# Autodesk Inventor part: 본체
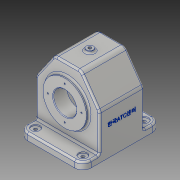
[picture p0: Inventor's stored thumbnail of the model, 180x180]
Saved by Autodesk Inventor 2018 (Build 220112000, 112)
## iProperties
Created: 2022-12
Part Number: 본체
Material: 알루미늄 6061
Document SubType Name: Modeling
Designer: 강의실04
Density: 2.7 g/cm^3
Appearance: 알루미늄 - 평지
Mass: 937.278 g
Surface Area: 1065.24 cm^2
Volume: 347.14 cm^3
Author: 강의실04
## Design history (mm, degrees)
sketch "스케치1"
  geometry: L1 (-55, 12)-(55, 12); L2 (55, 12)-(55, -65); L3 (55, -65)-(-55, -65); L4 (-55, -65)-(-55, 12); L5 (-55, 12)-(-23.491, 57); L6 (-23.491, 57)-(23.491, 57); L7 (23.491, 57)-(55, 12); 3 further points
  constraints: 14 end point, 2 horizontal, 2 midpoint, 2 parallel, 2 vertical alignment, 1 perpendicular
  dimensions: "d1" = 65 distance from line of L3 point (0, 0); "d2" = 77 distance of L3.end L1.start; "d3" = 110 distance of L2.end L3.end; "d4" = 35 deg angle of L5 L4; "d5" = 122 distance between parallel lines of L3 L6
extrude "돌출1" new body sketch "스케치1" stored distance "d6" = 77; taper "d7" = 0 deg
feature "쉘1" dims "d8" = 5
sketch "스케치2"
  geometry: L1 (5, -5)-(5, -72) reference; L2 (5, -72)-(105, -72) reference; L3 (105, -72)-(105, -5) reference; L4 (105, -5)-(5, -5) reference; L5 (0, -77)-(0, 0) reference; L6 (0, 0)-(110, 0) reference; L7 (110, 0)-(110, -77) reference; L8 (110, -77)-(0, -77) reference; L9 (0, -105.5)-(110, -105.5); L10 (110, -105.5)-(110, 28.5); L11 (110, 28.5)-(0, 28.5); L12 (0, 28.5)-(0, -105.5); L13 (0, -105.5)-(110, 28.5); L14 (110, -105.5)-(0, 28.5); 1 further point
  constraints: 12 end point, 2 midpoint, 2 parallel, 1 horizontal, 1 perpendicular, 1 point on line
  dimensions: "d9" = 134 distance of L9.end L10.end
extrude "돌출2" join sketch "스케치2" distance "d10" = 12; taper "d11" = 0 deg
node "작업 평면1"
sketch "스케치3"
  geometry: C1 r 6 at (0, 0); 1 further point
  constraints: 1 centre point, 1 coincident
  dimensions: "d13" = 12 diameter of C1
extrude "돌출3" join sketch "스케치3" stored distance "d14" = 12; taper "d15" = 0 deg
sketch "스케치4"
  geometry: 1 further point
hole "구멍1" sketch "스케치4" at (0, 0) diameter "d16" = 5.188; stored, may be unused: countersink angle "d20" = 90 deg, drill point angle "d22" = 118 deg; dims "d17" = 12, "d18" = 4, "d19" = 2, "d21" = 16
sketch "스케치5"
  geometry: C1 r 37.5 at (0, 0); 1 further point
  constraints: 1 centre point, 1 coincident
  dimensions: "d23" = 75 diameter of C1
extrude "돌출4" join sketch "스케치5" distance "d24" = 5; taper "d25" = 0 deg
sketch "스케치6"
  geometry: C1 r 31 at (0, 0); 1 further point
  constraints: 1 centre point, 1 coincident
  dimensions: "d26" = 62 diameter of C1
extrude "돌출5" join sketch "스케치6" distance "d27" = 10; taper "d28" = 0 deg
sketch "스케치7"
  geometry: L1 (10.424, 33.5)-(-65, 33.5) reference; L2 (0, 33.5)-(0, 0); L3 (52, 33.5)-(10.424, 33.5) reference; L4 (41, 33.5)-(27, 19.5); L5 (27, 19.5)-(0, 19.5); L6 (37.5, 43.5)-(-37.5, 43.5) reference; L7 (41, 33.5)-(0, 33.5)
  constraints: 8 end point, 3 point on line, 2 perpendicular, 1 vertical
  dimensions: "d29" = 54 diameter of L4.end L2; "d30" = 135 deg angle of L3 L4; "d31" = 24 distance between parallel lines of L5 L6
revolve "회전1" sketch "스케치7" stored, may be unused: angle "d32" = 90 deg
sketch "스케치8"
  geometry: C1 r 20 at (0, 0); 1 further point
  constraints: 1 centre point, 1 coincident
  dimensions: "d33" = 40 diameter of C1
extrude "돌출6" cut sketch "스케치8" extent not by distance; stored distance "d34" = 10; taper "d35" = 0 deg
sketch "스케치9" dims "d36" = 58
  geometry: 3 further points
  constraints: 2 vertical alignment, 1 coincident, 2 other
hole "구멍2" sketch "스케치9" at (0, 29) diameter "d37" = 2.459; stored, may be unused: countersink angle "d41" = 90 deg, drill point angle "d43" = 118 deg; dims "d38" = 6, "d39" = 4, "d40" = 2, "d42" = 8
sketch "스케치10" dims "d47" = 52
  geometry: 3 further points
  constraints: 2 vertical alignment, 1 coincident, 2 other
hole "구멍3" sketch "스케치10" at (0, 26) diameter "d48" = 2.459; stored, may be unused: countersink angle "d52" = 90 deg, drill point angle "d54" = 118 deg; dims "d49" = 6, "d50" = 4, "d51" = 2, "d53" = 8
fillet "모깎기1" dims "d58" = 14
sketch "스케치11"
  geometry: L1 (14, 105.5)-(96, 105.5) reference; L2 (110, 91.5)-(110, 77) reference; L3 (110, 77)-(110, 0) reference; L4 (110, 0)-(0, 0) reference; L5 (0, -14.5)-(0, 0) reference; L6 (96, -28.5)-(14, -28.5) reference; L7 (110, 0)-(110, -14.5) reference; L8 (0, 77)-(0, 91.5) reference; L9 (0, 77)-(110, 77) reference; L10 (0, 0)-(0, 77) reference; L11 (105, 5)-(105, 72) reference; L12 (105, 72)-(5, 72) reference; L13 (5, 72)-(5, 5) reference; L14 (5, 5)-(105, 5) reference; A1 r 14 centre (14, 91.5) between (14, 105.5) and (0, 91.5) reference; A2 r 14 centre (96, 91.5) between (110, 91.5) and (96, 105.5) reference; A3 r 14 centre (14, -14.5) between (0, -14.5) and (14, -28.5) reference; A4 r 14 centre (96, -14.5) between (96, -28.5) and (110, -14.5) reference; 1 further point
hole "구멍4" sketch "스케치11" at (14, -14.5), (96, -14.5), (14, 91.5), (96, 91.5) diameter "d59" = 5.5; stored, may be unused: countersink angle "d63" = 90 deg, drill point angle "d65" = 118 deg; dims "d60" = 6, "d61" = 15, "d62" = 2, "d64" = 8
node "작업 평면2"
sketch "스케치12"
  geometry: L1 (-14.5, -77)-(-28.5, -77) reference; 2 further points
  constraints: 1 vertical alignment, 1 other
  dimensions: "d67" = 50 distance from line of L1 point (38.5, -27)
feature "엠보싱1" sketch "스케치12" dims "d1" = 65, "d2" = 77, "d3" = 110, "d4" = 35 deg, "d5" = 122, "d9" = 134, "d68" = 0.5, "d69" = 0
fillet "모깎기2" dims "d70" = 3
fillet "모깎기3" dims "d71" = 5
fillet "모깎기4" dims "d72" = 3
fillet "모깎기5" dims "d73" = 10
fillet "모깎기6" dims "d74" = 3
fillet "모깎기7" dims "d75" = 3
chamfer "모따기1" distance "d76" = 1; stored, may be unused: second distance "d77" = 2, angle "d78" = 45 deg
node "솔리드1"
pattern_circular "원형 패턴1" dims angle "d45" = 360 deg
pattern_circular "원형 패턴2" dims angle "d56" = 360 deg
node "절단 모서리 투영1"
node "절단 모서리 투영2"
other parameters: "d12" = 61, "d66" = 12.5
